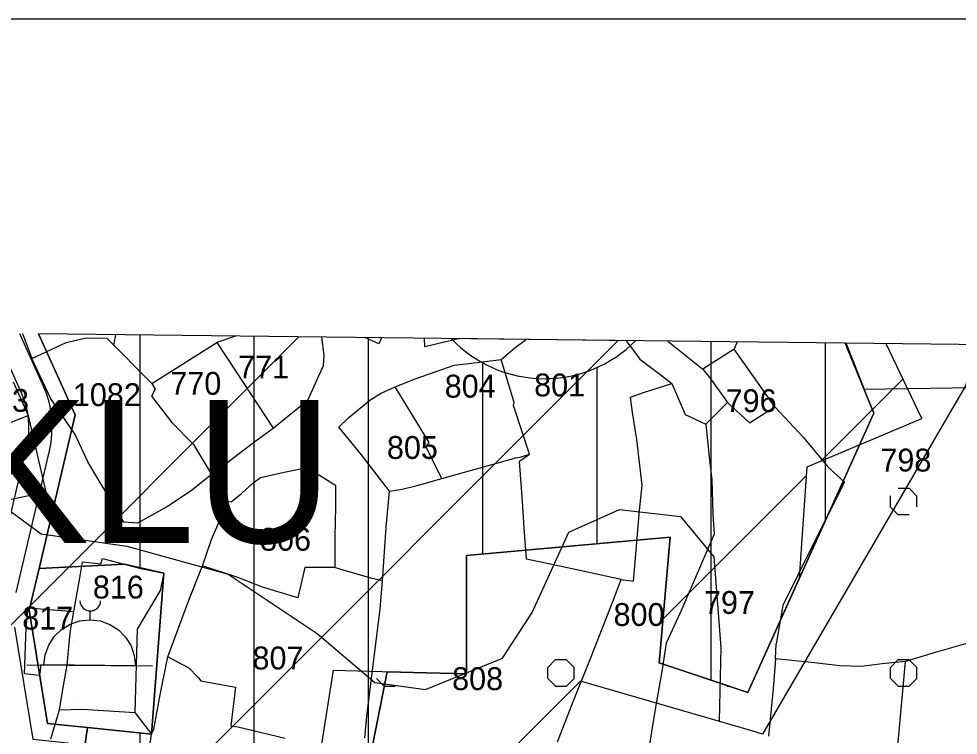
# Model space of a CAD drawing. Extents: x 410727 to 412947, y 4463506 to 4466382.
# Drawn here: x 411199.7 to 411364.1, y 4466256.2 to 4466381.6 of the extents above; entities that cross this region are included whole.
import ezdxf

# ---------------------------------------------------------------- set-up
doc = ezdxf.new("R2010")
doc.units = 0
for name, color, linetype in [('ADAKENARI', 7, 'Continuous'), ('KALDIRIM', 7, 'Continuous'), ('KDS_PARSEL_NO', 7, 'Continuous'), ('KDS_PL', 7, 'Continuous'), ('LJ_ÇERÇEVE', 7, 'Continuous'), ('PL_KA_TARIM_OZEL', 7, 'Continuous'), ('PL_KON_MEV_050', 7, 'Continuous'), ('PL_SAY_DINI_TESIS', 7, 'Continuous'), ('sembol', 7, 'Continuous'), ('SNR_KOY_YAZ', 7, 'Continuous'), ('SNR_KOYLER', 7, 'Continuous'), ('SNR_TR_AZGELISME', 7, 'Continuous'), ('TR_AZYOGUNLUK_MESKUN', 7, 'Continuous'), ('TR_DINITESIS', 7, 'Continuous'), ('TR_OZELMAHSUL', 7, 'Continuous'), ('Yerlesime_uygunluk_sınırı', 7, 'Continuous')]:
    doc.layers.add(name, color=color, linetype=linetype)

msp = doc.modelspace()

# ---------------------------------------------------------------- linework, layer by layer
at = {"layer": 'ADAKENARI'}
for points in [[(411349.39, 4466312.57), (411327.31, 4466263.68), (411311.77, 4466268.86), (411313.71, 4466290.89), (411278.08, 4466287.65), (411278.08, 4466266.92), (411264.19, 4466267.3), (411248.2, 4466186.88), (411205.64, 4466196.2), (411206.84, 4466224.72), (411211.69, 4466257.54), (411222.9, 4466256.36), (411225.07, 4466284.56), (411218.16, 4466286.13), (411203.22, 4466285.38), (411209.55, 4466312.29), (411203.13, 4466326.47)], [(411344.35, 4466324.82), (411349.39, 4466312.57)], [(411211.69, 4466257.54), (411222.9, 4466256.36), (411225.07, 4466284.56), (411218.16, 4466286.13), (411203.22, 4466285.38)], [(411211.69, 4466257.54), (411204.73, 4466258.27), (411201.49, 4466278.06), (411203.22, 4466285.38)]]:
    msp.add_lwpolyline(points, dxfattribs=at)
at = {"layer": 'KALDIRIM'}
for points in [[(411195.25, 4466282.09), (411201.09, 4466306.9), (411201.31, 4466308.04), (411201.43, 4466309.19), (411201.46, 4466310.34), (411201.4, 4466311.5), (411201.24, 4466312.65), (411200.99, 4466313.78), (411200.64, 4466314.88), (411200.21, 4466315.96), (411195.41, 4466326.56)], [(411199.82, 4466326.51), (411203.85, 4466317.61), (411203.85, 4466317.61), (411204.41, 4466316.23), (411204.85, 4466314.81), (411205.18, 4466313.36), (411205.38, 4466311.89), (411205.46, 4466310.4), (411205.42, 4466308.92), (411205.26, 4466307.44), (411204.98, 4466305.98), (411204.98, 4466305.98), (411199.14, 4466281.17)], [(411198.93, 4466275.12), (411202.14, 4466255.53), (411208.26, 4466254.88), (411203.85, 4466225), (411202.32, 4466188.77), (411202.93, 4466148.93), (411203.04, 4466147.17), (411203.33, 4466145.44), (411203.79, 4466143.74), (411204.42, 4466142.09), (411205.21, 4466140.52), (411206.15, 4466139.03), (411207.24, 4466137.64), (411208.46, 4466136.37), (411279.4, 4466069.3), (411313.49, 4466025.68), (411330.24, 4466015.11), (411340.12, 4466013.05)]]:
    msp.add_lwpolyline(points, dxfattribs=at)
at = {"layer": 'KDS_PL'}
for p, q in [((411200.31, 4466326.5), (411201.98, 4466322.13)), ((411207.94, 4466324.94), (411211.49, 4466325.77)), ((411211.49, 4466325.77), (411215.06, 4466325.67)), ((411215.06, 4466325.67), (411222.94, 4466317.78)), ((411216.29, 4466324.44), (411216.64, 4466326.31)), ((411237.6, 4466326.07), (411234.35, 4466324.95)), ((411253.15, 4466322.7), (411252.72, 4466325.89)), ((411262.69, 4466324.71), (411260.25, 4466325.8)), ((411263.17, 4466325.77), (411262.69, 4466324.71)), ((411270.77, 4466324.16), (411270.73, 4466325.68)), ((411276.88, 4466325.61), (411273.19, 4466324.78)), ((411286.6, 4466324.04), (411288.53, 4466325.47)), ((411305.97, 4466325.27), (411307.14, 4466323.76)), ((411313.29, 4466325.18), (411313.61, 4466324.93)), ((411325.46, 4466325.04), (411324.9, 4466323.75)), ((411201.98, 4466322.13), (411207.94, 4466324.94)), ((411222.94, 4466317.78), (411234.35, 4466324.95)), ((411234.35, 4466324.95), (411237.62, 4466319.97)), ((411273.19, 4466324.78), (411270.77, 4466324.16)), ((411284.1, 4466321.94), (411286.6, 4466324.04)), ((411307.14, 4466323.76), (411307.91, 4466322.65)), ((411313.61, 4466324.93), (411319.41, 4466320.29)), ((411324.9, 4466323.75), (411319.41, 4466320.29)), ((411329.01, 4466318.01), (411324.9, 4466323.75)), ((411347.75, 4466316.7), (411344.52, 4466324.81)), ((411205.31, 4466315.08), (411201.98, 4466322.13)), ((411253.02, 4466320.91), (411253.15, 4466322.7)), ((411278.39, 4466321.28), (411284.1, 4466321.94)), ((411286.38, 4466314.45), (411284.1, 4466321.94)), ((411307.91, 4466322.65), (411308.4, 4466322)), ((411308.4, 4466322), (411311.64, 4466319.54)), ((411250.31, 4466314.96), (411253.02, 4466320.91)), ((411269.25, 4466318.65), (411275.89, 4466320.97)), ((411275.89, 4466320.97), (411278.39, 4466321.28)), ((411319.41, 4466320.29), (411320.68, 4466318.74)), ((411237.62, 4466319.97), (411244.22, 4466309.92)), ((411265.59, 4466317.18), (411269.25, 4466318.65)), ((411311.64, 4466319.54), (411314.02, 4466317.75)), ((411320.68, 4466318.74), (411323.74, 4466314.46)), ((411198.69, 4466318.04), (411201.31, 4466312.17)), ((411222.94, 4466317.78), (411223.56, 4466316.77)), ((411263.09, 4466316.06), (411265.59, 4466317.18)), ((411271.52, 4466307.41), (411265.59, 4466317.18)), ((411309.02, 4466316.2), (411314.02, 4466317.75)), ((411314.02, 4466317.75), (411316.33, 4466312.35)), ((411332.03, 4466313.68), (411329.01, 4466318.01)), ((411363, 4466316.93), (411347.75, 4466316.7)), ((411370.43, 4466317.16), (411363, 4466316.93)), ((411223.56, 4466316.77), (411222.92, 4466315.53)), ((411222.92, 4466315.53), (411226.46, 4466310.91)), ((411261.13, 4466314.82), (411263.09, 4466316.06)), ((411306.77, 4466315.37), (411309.02, 4466316.2)), ((411307.14, 4466312.69), (411306.77, 4466315.37)), ((411209.54, 4466308.82), (411205.31, 4466315.08)), ((411248.52, 4466313.43), (411250.31, 4466314.96)), ((411257.43, 4466311.83), (411261.13, 4466314.82)), ((411286.29, 4466313.89), (411286.38, 4466314.45)), ((411289.06, 4466305.41), (411286.29, 4466313.89)), ((411319.94, 4466310.62), (411323.74, 4466314.46)), ((411323.74, 4466314.46), (411327.61, 4466310.9)), ((411327.61, 4466310.9), (411332.03, 4466313.68)), ((411332.03, 4466313.68), (411337.06, 4466308.33)), ((411195.63, 4466309.92), (411201.31, 4466312.17)), ((411201.31, 4466312.17), (411204.43, 4466298.75)), ((411244.22, 4466309.92), (411248.52, 4466313.43)), ((411307.88, 4466307.97), (411307.14, 4466312.69)), ((411316.33, 4466312.35), (411319.94, 4466310.62)), ((411226.46, 4466310.91), (411230.26, 4466307.08)), ((411255.69, 4466310.13), (411257.43, 4466311.83)), ((411319.94, 4466310.62), (411320.53, 4466304.94)), ((411211.77, 4466304.07), (411209.54, 4466308.82)), ((411240.97, 4466307.61), (411244.22, 4466309.92)), ((411259.7, 4466305.27), (411255.69, 4466310.13)), ((411230.26, 4466307.08), (411233.43, 4466301.83)), ((411233.43, 4466301.83), (411240.97, 4466307.61)), ((411270.94, 4466306.79), (411271.52, 4466307.41)), ((411308.8, 4466299.98), (411307.88, 4466307.97)), ((411337.06, 4466308.33), (411341.32, 4466303.15)), ((411273.26, 4466302.01), (411270.94, 4466306.79)), ((411287.36, 4466304.14), (411289.06, 4466305.41)), ((411287.43, 4466304.88), (411289.06, 4466305.41)), ((411218.05, 4466293.51), (411211.77, 4466304.07)), ((411264.6, 4466298.93), (411259.7, 4466305.27)), ((411273.76, 4466301.12), (411286.72, 4466304.73)), ((411286.72, 4466304.73), (411287.43, 4466304.88)), ((411287.83, 4466297.08), (411287.36, 4466304.14)), ((411320.53, 4466304.94), (411321.02, 4466300.9)), ((411242.02, 4466301.33), (411245.85, 4466302.17)), ((411245.85, 4466302.17), (411249.64, 4466302.94)), ((411249.64, 4466302.94), (411250.04, 4466302.97)), ((411250.04, 4466302.97), (411250.91, 4466302.6)), ((411250.91, 4466302.6), (411255.13, 4466299.95)), ((411273.76, 4466301.12), (411273.26, 4466302.01)), ((411341.32, 4466303.15), (411344.26, 4466300.51)), ((411233.43, 4466301.83), (411229.85, 4466298.97)), ((411240.67, 4466300.29), (411242.02, 4466301.33)), ((411269.41, 4466299.92), (411273.76, 4466301.12)), ((411321.02, 4466300.9), (411321.2, 4466294.89)), ((411344.26, 4466300.51), (411338.45, 4466289.05)), ((411204.43, 4466298.75), (411190.83, 4466295.81)), ((411229.85, 4466298.97), (411225.7, 4466296.21)), ((411238.66, 4466298.53), (411240.67, 4466300.29)), ((411255.13, 4466299.95), (411255.13, 4466296.09)), ((411263.98, 4466292.58), (411264.6, 4466298.93)), ((411264.6, 4466298.93), (411266.79, 4466299.27)), ((411266.79, 4466299.27), (411269.41, 4466299.92)), ((411308.34, 4466295.5), (411308.8, 4466299.98)), ((411236.04, 4466296.83), (411236.35, 4466297.17)), ((411236.35, 4466297.17), (411236.84, 4466297.02)), ((411236.84, 4466297.02), (411238.66, 4466298.53)), ((411288.17, 4466292.51), (411287.83, 4466297.08)), ((411225.7, 4466296.21), (411220.47, 4466293.32)), ((411233.42, 4466290.45), (411235.64, 4466295.6)), ((411235.64, 4466295.6), (411236.04, 4466296.83)), ((411255.13, 4466296.09), (411254.98, 4466291)), ((411307.75, 4466288.56), (411308.34, 4466295.5)), ((411217.14, 4466295.09), (411217.6, 4466294.43)), ((411321.2, 4466294.89), (411321.42, 4466291.4)), ((411220.47, 4466293.32), (411218.05, 4466293.51)), ((411263.37, 4466283.23), (411263.98, 4466292.58)), ((411288.57, 4466286.99), (411288.17, 4466292.51)), ((411254.98, 4466291), (411254.98, 4466285.57)), ((411321.42, 4466291.4), (411319.57, 4466287.05)), ((411231.81, 4466285.85), (411233.42, 4466290.45)), ((411338.45, 4466289.05), (411333.42, 4466278.91)), ((411307.32, 4466283.14), (411307.75, 4466288.56)), ((411210.32, 4466283.38), (411210.8, 4466286.55)), ((411210.8, 4466286.55), (411214.02, 4466286.17)), ((411214.02, 4466286.17), (411214.34, 4466287.14)), ((411214.34, 4466287.14), (411221.05, 4466285.37)), ((411229.42, 4466279.84), (411231.81, 4466285.85)), ((411238.01, 4466283.81), (411231.81, 4466285.85)), ((411249.73, 4466285.57), (411248.5, 4466280.27)), ((411254.98, 4466285.57), (411249.73, 4466285.57)), ((411256.3, 4466285.17), (411254.98, 4466285.57)), ((411296.53, 4466285.33), (411288.57, 4466286.99)), ((411319.57, 4466287.05), (411315.74, 4466278.23)), ((411221.05, 4466285.37), (411225.07, 4466284.56)), ((411225.07, 4466284.56), (411224.43, 4466281.51)), ((411261.55, 4466283.63), (411256.3, 4466285.17)), ((411305.13, 4466283.47), (411296.53, 4466285.33)), ((411209.3, 4466277.86), (411210.32, 4466283.38)), ((411242.36, 4466282.09), (411238.01, 4466283.81)), ((411263.37, 4466283.23), (411261.55, 4466283.63)), ((411262.93, 4466278.23), (411263.37, 4466283.23)), ((411303.68, 4466279.59), (411305.13, 4466283.47)), ((411305.13, 4466283.47), (411307.32, 4466283.14)), ((411224.43, 4466281.51), (411220.4, 4466274.75)), ((411248.5, 4466280.27), (411242.36, 4466282.09)), ((411225.77, 4466269.93), (411229.42, 4466279.84)), ((411299.86, 4466269.9), (411303.68, 4466279.59)), ((411200.94, 4466275.03), (411201.31, 4466278.52)), ((411201.31, 4466278.52), (411209.3, 4466277.86)), ((411208.66, 4466274.16), (411209.3, 4466277.86)), ((411261.95, 4466270.36), (411262.93, 4466278.23)), ((411315.74, 4466278.23), (411313, 4466272.31)), ((411333.42, 4466278.91), (411332.26, 4466272.18)), ((411200.69, 4466266.91), (411200.94, 4466275.03)), ((411208.17, 4466268.47), (411208.66, 4466274.16)), ((411220.4, 4466274.75), (411219.98, 4466260.16)), ((411367.44, 4466272.78), (411360.1, 4466270.68)), ((411313, 4466272.31), (411312.26, 4466267.37)), ((411332.15, 4466269.59), (411332.26, 4466272.18)), ((411224.44, 4466263.24), (411225.77, 4466269.93)), ((411225.77, 4466269.93), (411227.09, 4466269.19)), ((411227.09, 4466269.19), (411229.44, 4466267.96)), ((411260.59, 4466259.54), (411261.95, 4466270.36)), ((411296.56, 4466261.63), (411299.86, 4466269.9)), ((411332.15, 4466269.59), (411331.74, 4466264.35)), ((411338.48, 4466268.92), (411332.15, 4466269.59)), ((411354.89, 4466269.12), (411350.85, 4466268.66)), ((411353.81, 4466256.92), (411354.89, 4466269.12)), ((411360.1, 4466270.68), (411354.89, 4466269.12)), ((411203.56, 4466268.53), (411203.31, 4466266.66)), ((411208.17, 4466268.47), (411203.56, 4466268.53)), ((411207.53, 4466264.88), (411208.17, 4466268.47)), ((411229.44, 4466267.96), (411231.13, 4466266.26)), ((411343.39, 4466268.32), (411338.48, 4466268.92)), ((411347.21, 4466268.24), (411343.39, 4466268.32)), ((411350.85, 4466268.66), (411347.21, 4466268.24)), ((411203.31, 4466266.66), (411200.69, 4466266.91)), ((411231.13, 4466266.26), (411231.53, 4466265.74)), ((411312.26, 4466267.37), (411311.12, 4466261.11)), ((411206.83, 4466260.64), (411207.53, 4466264.88)), ((411231.53, 4466265.74), (411237.64, 4466264.63)), ((411237.64, 4466264.63), (411236.78, 4466257.81)), ((411331.74, 4466264.35), (411330.92, 4466256.03)), ((411223.33, 4466257.25), (411224.44, 4466263.24)), ((411293.97, 4466255.03), (411296.56, 4466261.63)), ((411311.12, 4466261.11), (411310.07, 4466254.63)), ((411205.28, 4466255.54), (411206.83, 4466260.64)), ((411206.83, 4466260.64), (411210.85, 4466260.75)), ((411210.85, 4466260.75), (411219.98, 4466260.16)), ((411219.98, 4466260.16), (411222.9, 4466256.36)), ((411260.25, 4466255.71), (411260.59, 4466259.54)), ((411236.78, 4466257.81), (411238.04, 4466257.69)), ((411238.04, 4466257.69), (411246.31, 4466255.68)), ((411222.4, 4466252.78), (411222.9, 4466256.36)), ((411222.9, 4466256.36), (411223.33, 4466257.25)), ((411352.06, 4466237.94), (411353.81, 4466256.92))]:
    msp.add_line(p, q, dxfattribs=at)
at = {"layer": 'LJ_ÇERÇEVE'}
msp.add_lwpolyline([(410732.32, 4466381.6), (412946.74, 4466381.6), (412946.74, 4463506.16), (410732.32, 4463506.16)], close=True, dxfattribs=at)
at = {"layer": 'PL_KA_TARIM_OZEL'}
msp.add_lwpolyline([(411693.82, 4466320.72), (411344.35, 4466324.82), (411349.39, 4466312.57), (411340.91, 4466293.79), (411327.31, 4466263.68), (411320.91, 4466265.81), (411311.77, 4466268.86), (411313.71, 4466290.89), (411300.91, 4466289.72), (411280.91, 4466287.91), (411278.08, 4466287.65), (411278.08, 4466266.92), (411264.19, 4466267.3), (411260.91, 4466250.81), (411256.24, 4466227.32), (411248.2, 4466186.88), (411240.91, 4466188.47), (411220.91, 4466192.86), (411205.64, 4466196.2), (411205.32, 4466188.73), (411205.95, 4466147.79)], dxfattribs=at)
at = {"layer": 'PL_KON_MEV_050'}
msp.add_lwpolyline([(411344.35, 4466324.82), (411203.13, 4466326.47), (411209.55, 4466312.29), (411203.22, 4466285.38), (411218.16, 4466286.13), (411225.07, 4466284.56), (411222.9, 4466256.36), (411211.69, 4466257.54), (411206.84, 4466224.72), (411205.64, 4466196.2), (411248.2, 4466186.88), (411264.19, 4466267.3), (411278.08, 4466266.92), (411278.08, 4466287.65), (411313.71, 4466290.89), (411311.77, 4466268.86), (411327.31, 4466263.68), (411349.39, 4466312.57), (411344.35, 4466324.82)], dxfattribs=at)
at = {"layer": 'PL_SAY_DINI_TESIS'}
msp.add_lwpolyline([(411211.69, 4466257.54), (411222.9, 4466256.36), (411225.07, 4466284.56), (411218.16, 4466286.13), (411203.22, 4466285.38), (411201.49, 4466278.06), (411204.73, 4466258.27), (411211.69, 4466257.54)], dxfattribs=at)
at = {"layer": 'sembol'}
for p, q in [((411212.16, 4466276.42), (411212.17, 4466277.97)), ((411201.08, 4466268.52), (411223.08, 4466268.31))]:
    msp.add_line(p, q, dxfattribs=at)
for points in [[(411307.66, 4466325.25), (411275.37, 4466325.63)], [(411204.08, 4466268.5), (411204.3, 4466270.27), (411204.91, 4466271.96), (411205.88, 4466273.47), (411207.15, 4466274.72), (411208.68, 4466275.66), (411210.38, 4466276.23), (411212.16, 4466276.42), (411213.94, 4466276.2), (411215.62, 4466275.59), (411217.13, 4466274.62), (411218.38, 4466273.34), (411219.32, 4466271.82), (411219.9, 4466270.12), (411220.08, 4466268.34), (411204.08, 4466268.5)]]:
    msp.add_lwpolyline(points, dxfattribs=at)
for centre, radius, start, end in [((411291.7, 4466341.1), 22.5, 223.4624, 315.1946), ((411212.19, 4466279.75), 1.81, 181.9335, 358.0665)]:
    msp.add_arc(centre, radius, start, end, dxfattribs=at)
at = {"layer": 'SNR_KOYLER'}
for p, q in [((411357.76, 4466311.62), (411351.51, 4466324.73)), ((411337.68, 4466303.2), (411357.76, 4466311.62)), ((411336.38, 4466283.76), (411337.68, 4466303.2)), ((411278.08, 4466287.65), (411313.71, 4466290.89)), ((411313.71, 4466290.89), (411311.77, 4466268.86)), ((411278.08, 4466266.92), (411278.08, 4466287.65)), ((411327.31, 4466263.68), (411336.38, 4466283.76)), ((411248.28, 4466226.11), (411254.76, 4466267.57)), ((411254.76, 4466267.57), (411278.08, 4466266.92)), ((411311.77, 4466268.86), (411327.31, 4466263.68))]:
    msp.add_line(p, q, dxfattribs=at)
at = {"layer": 'SNR_TR_AZGELISME'}
for p, q in [((411013.12, 4466090.34), (411248.72, 4466325.94)), ((411069.58, 4466090.23), (411304.63, 4466325.28)), ((411340.15, 4466304.23), (411354.46, 4466318.54)), ((411340.15, 4466304.23), (411354.46, 4466318.54)), ((411312.44, 4466276.52), (411337.57, 4466301.66))]:
    msp.add_line(p, q, dxfattribs=at)
at = {"layer": 'TR_AZYOGUNLUK_MESKUN'}
for p, q in [((411220.91, 4466285.51), (411220.91, 4466326.26)), ((411240.91, 4466188.47), (411240.91, 4466326.03)), ((411260.91, 4466250.81), (411260.91, 4466325.79)), ((411320.91, 4466265.81), (411320.91, 4466325.09)), ((411340.91, 4466293.79), (411340.91, 4466324.86)), ((411280.91, 4466287.91), (411280.91, 4466321.36)), ((411300.91, 4466289.72), (411300.91, 4466320.58)), ((411220.91, 4466192.86), (411220.91, 4466256.57))]:
    msp.add_line(p, q, dxfattribs=at)
at = {"layer": 'TR_DINITESIS'}
for p, q in [((411208.62, 4466284.02), (411208.62, 4466284.02)), ((411218.62, 4466284.02), (411218.62, 4466284.02)), ((411209.09, 4466272.75), (411209.09, 4466272.75)), ((411219.09, 4466272.75), (411219.09, 4466272.75)), ((411209.09, 4466262.75), (411209.09, 4466262.75)), ((411219.09, 4466262.75), (411219.09, 4466262.75))]:
    msp.add_line(p, q, dxfattribs=at)
at = {"layer": 'TR_OZELMAHSUL'}
for p, q in [((411353.64, 4466299.42), (411355.56, 4466299.42)), ((411356.92, 4466298.06), (411355.57, 4466299.41)), ((411352.29, 4466296.15), (411352.29, 4466298.07)), ((411356.91, 4466296.15), (411356.91, 4466298.07)), ((411353.65, 4466294.79), (411352.3, 4466296.14)), ((411353.64, 4466294.8), (411355.56, 4466294.8)), ((411292.28, 4466268.06), (411293.64, 4466269.42)), ((411293.64, 4466269.42), (411295.56, 4466269.42)), ((411296.92, 4466268.06), (411295.57, 4466269.41)), ((411352.28, 4466268.06), (411353.64, 4466269.42)), ((411353.64, 4466269.42), (411355.56, 4466269.42)), ((411356.92, 4466268.06), (411355.57, 4466269.41)), ((411292.29, 4466266.15), (411292.29, 4466268.07)), ((411296.91, 4466266.15), (411296.91, 4466268.07)), ((411352.29, 4466266.15), (411352.29, 4466268.07)), ((411356.91, 4466266.15), (411356.91, 4466268.07)), ((411263.65, 4466264.79), (411262.3, 4466266.14)), ((411293.65, 4466264.79), (411292.3, 4466266.14)), ((411295.55, 4466264.79), (411296.91, 4466266.15)), ((411353.65, 4466264.79), (411352.3, 4466266.14)), ((411355.55, 4466264.79), (411356.91, 4466266.15)), ((411263.64, 4466264.8), (411265.56, 4466264.8)), ((411293.64, 4466264.8), (411295.56, 4466264.8)), ((411323.64, 4466264.8), (411323.96, 4466264.8)), ((411353.64, 4466264.8), (411355.56, 4466264.8))]:
    msp.add_line(p, q, dxfattribs=at)
at = {"layer": 'Yerlesime_uygunluk_sınırı'}
for points in [[(411168.47, 4466326.88), (411168.55, 4466326.8), (411177.59, 4466318.33), (411189.83, 4466301.51), (411203.59, 4466291.42), (411218.58, 4466289.28), (411236.32, 4466284.38), (411251.92, 4466273.98), (411262.02, 4466265.42), (411270.89, 4466264.19), (411284.35, 4466269.7), (411289.54, 4466277.65), (411295.97, 4466291.72), (411304.84, 4466295.7), (411315.54, 4466294.48), (411321.36, 4466287.44), (411322.58, 4466271.54), (411322.28, 4466258.69)], [(411367.59, 4466324.54), (411367.57, 4466324.45), (411365.4, 4466317.37), (411329.85, 4466256.4), (411327.98, 4466256.94), (411298.02, 4466265.64), (411235.39, 4466203.01), (411292.89, 4466117.8), (411249.96, 4466080.27), (411288.76, 4466053.15), (411335.49, 4466003.87), (411401.49, 4466010.55), (411454, 4465988), (411518.19, 4465927.25), (411576.49, 4465880.17), (411546.8, 4465853.02), (411462.76, 4465826.95), (411417.87, 4465818.6), (411360.95, 4465816.44), (411257.66, 4465822.32), (411198.74, 4465810.19), (411081.53, 4465694.24)]]:
    msp.add_lwpolyline(points, dxfattribs=at)

# ---------------------------------------------------------------- texts
at = {"layer": 'KDS_PARSEL_NO'}
for s, p in [('771', (411238.07, 4466318.66)), ('770', (411226.2, 4466315.78)), ('804', (411274.24, 4466315.29)), ('801', (411289.9, 4466315.5)), ('763', (411192.53, 4466312.8)), ('1082', (411209.14, 4466313.8)), ('796', (411323.42, 4466312.75)), ('805', (411264.12, 4466304.56)), ('798', (411350.51, 4466302.35)), ('806', (411241.91, 4466288.49)), ('816', (411212.64, 4466280.12)), ('797', (411319.63, 4466277.43)), ('800', (411303.8, 4466275.32)), ('817', (411200.28, 4466274.69)), ('807', (411240.59, 4466267.71)), ('808', (411275.54, 4466264.09))]:
    msp.add_text(s, height=4, dxfattribs=at).set_placement(p)
at = {"layer": 'SNR_KOY_YAZ'}
msp.add_text('GOYNUKLU', height=25, dxfattribs=at).set_placement((411067.05, 4466289.86))

doc.saveas('drawing.dxf')
